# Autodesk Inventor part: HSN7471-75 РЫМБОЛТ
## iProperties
Created: 2011-02
Part Number: HSN7471-75 РЫМБОЛТ
Document SubType Name: Modeling
Designer: Чернышев Юрий
Mass: 16.9655 g
Surface Area: 54.8943 cm^2
Volume: 16.9655 cm^3
Density: 1 g/cm^3
Author: Чернышев Юрий
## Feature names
1. ExtrusionBlind1
2. RevolutionAngle1
3. Fillet1
4. Fillet2
5. Fillet3
